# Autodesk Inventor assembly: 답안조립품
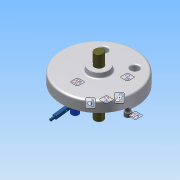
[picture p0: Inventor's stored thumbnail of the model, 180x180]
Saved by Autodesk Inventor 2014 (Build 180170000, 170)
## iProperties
Created: 2015-06
Part Number: 답안조립품
Document SubType Name: Assembly
Designer: Administrator
Author: Administrator
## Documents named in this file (10)
- C:\Documents and Settings\Administrator\바탕 화면\450631V1020\답안조립품.iam
- C:\Documents and Settings\Administrator\바탕 화면\450631V1020\1-본체.ipt
- C:\Documents and Settings\Administrator\바탕 화면\450631V1020\베어링62_22.ipt
- C:\Documents and Settings\Administrator\바탕 화면\450631V1020\축.ipt
- C:\Documents and Settings\Administrator\바탕 화면\450631V1020\멈춤링.ipt
- C:\Documents and Settings\Administrator\바탕 화면\450631V1020\슬라이더2.ipt
- C:\Documents and Settings\Administrator\바탕 화면\450631V1020\슬라이더.ipt
- C:\Documents and Settings\Administrator\바탕 화면\450631V1020\평행핀.ipt
- C:\Documents and Settings\Administrator\바탕 화면\450631V1020\덮개.ipt
- C:\Documents and Settings\Administrator\바탕 화면\450631V1020\M10x35.ipt
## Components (8 placed, 5 different names)
1. 1-본체:1
2. KS B 2023 62/22 - 22 x 50 x 14:1
3. KS B 1336 22 x 1.2:1
4. KS B 1320 B B 5 x  20:1 — 플러쉬:1
5. KS B 2023 62/22 - 22 x 50 x 14:2
6. KS B 1003 - 미터 M 10 x 35:1
7. KS B 1003 - 미터 M 10 x 35:2
8. KS B 1336 22 x 1.2:2
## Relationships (1: Flush 1)
- 플러쉬:1 [Flush]: KS B 1320 B B 5 x  20:1
